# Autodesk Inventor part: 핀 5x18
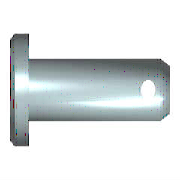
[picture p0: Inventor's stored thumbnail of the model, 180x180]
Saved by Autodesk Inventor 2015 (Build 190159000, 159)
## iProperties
Created: 2012-02
Part Number: 핀 5x18
Material: 강철
Description: 머리가 있는 클레비스 핀
Document SubType Name: Modeling
Standard: ISO 2341
Designer: test
Standard Revision: Second edition 1986-11-01
Standards Organization: ISO
Language: ko-KR
Size Designation: B - 5 x 18
Categories: <MemberInstance><Categories><Category DisplayName="조임쇠" InternalName="e4da775c-781d-43d5-af7c-5136215cf5a6" Mnemonic="FSTN"><Category DisplayName="핀" InternalNa
Density: 7.85 g/cm^3
Appearance: 주황색
IsCustomPart: 1
Author: test
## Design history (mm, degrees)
sketch "스케치1"
  geometry: L1 (-1.6, 0)-(-1.6, 4); L2 (-1.6, 4)-(0, 4); L3 (0, 4)-(0, 2.5); L4 (0, 2.5)-(18, 2.5); L5 (18, 2.5)-(18, 0); L6 (-1.6, 0)-(18, 0); L7 (-4, 0)-(17, 0) reference; L8 (0, -0.98)-(0, 3.08) reference; C1 r 0.6 at (15.1, 0)
  constraints: 12 end point, 3 parallel, 2 collinear, 2 perpendicular, 1 centre point, 1 point on line, 1 vertical
  dimensions: "d0" = 5 diameter of L4 L6 (= NND); "d1" = 8 diameter of L2 L6 (= KOD); "d2" = 1.6 distance of L1.end L2.end (= KOH); "d3" = 18 distance of L3.end L4.end (= NLG); "d5" = 2.9 distance from line of L5 C1.centre (= DIST); "d6" = 1.2 diameter of C1 (= BOR)
revolve "본체" stored, may be unused: angle "d4" = 90 deg
extrude "구멍" cut sketch "스케치1" stored distance "d7" = 5 (= NND); taper "d8" = 0 deg
workaxis "Work Axis1"
workplane "Work Plane1"
body "Solid1"
chamfer "모따기1" distance "d9" = 1 (= PHH2); stored, may be unused: angle "d10" = 45 deg (= FAWI2), second distance "d16" = 1 (= PHH2)
chamfer "모따기2" distance "d11" = 2 (= PHH1); stored, may be unused: angle "d12" = 30 deg (= FAWI1), second distance "d17" = 2 (= PHH1)
other parameters: "PHH1" = 2 [user parameter; used in 2 equation terms], "PHH2" = 1 [user parameter; used in 2 equation terms], "KOD" = 8 [user parameter; used in 1 equation term], "KOH" = 1.6 [user parameter; used in 1 equation term], "NND" = 5 [user parameter; used in 2 equation terms], "FAWI1" = 30 deg [user parameter; used in 1 equation term], "FAWI2" = 45 deg [user parameter; used in 1 equation term], "DIST" = 2.9 [user parameter; used in 1 equation term], "BOR" = 1.2 [user parameter; used in 1 equation term], "NLG" = 18 [user parameter; used in 1 equation term], "d13" = 0, "d14" = 0, "d27" = 0, "d28" = 0, "d29" = 0, "d30" = 0, "d31" = 0
